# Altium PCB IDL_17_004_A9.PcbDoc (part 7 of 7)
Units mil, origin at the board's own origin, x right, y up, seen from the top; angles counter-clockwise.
Board outline 9493.25 x 7199.68 mil, 6 copper layers (Top Layer - SIG1, Layer 2 - GND1, Layer 3 - PWR1, Layer 4 - PWR2, Layer 5 - GND2, Bottom Layer - SIG2), stack 60.592 mil thick; 403 components, 274 nets, 1834 pads, 1849 vias.
Unrouted connection lines stored in the file: 1.
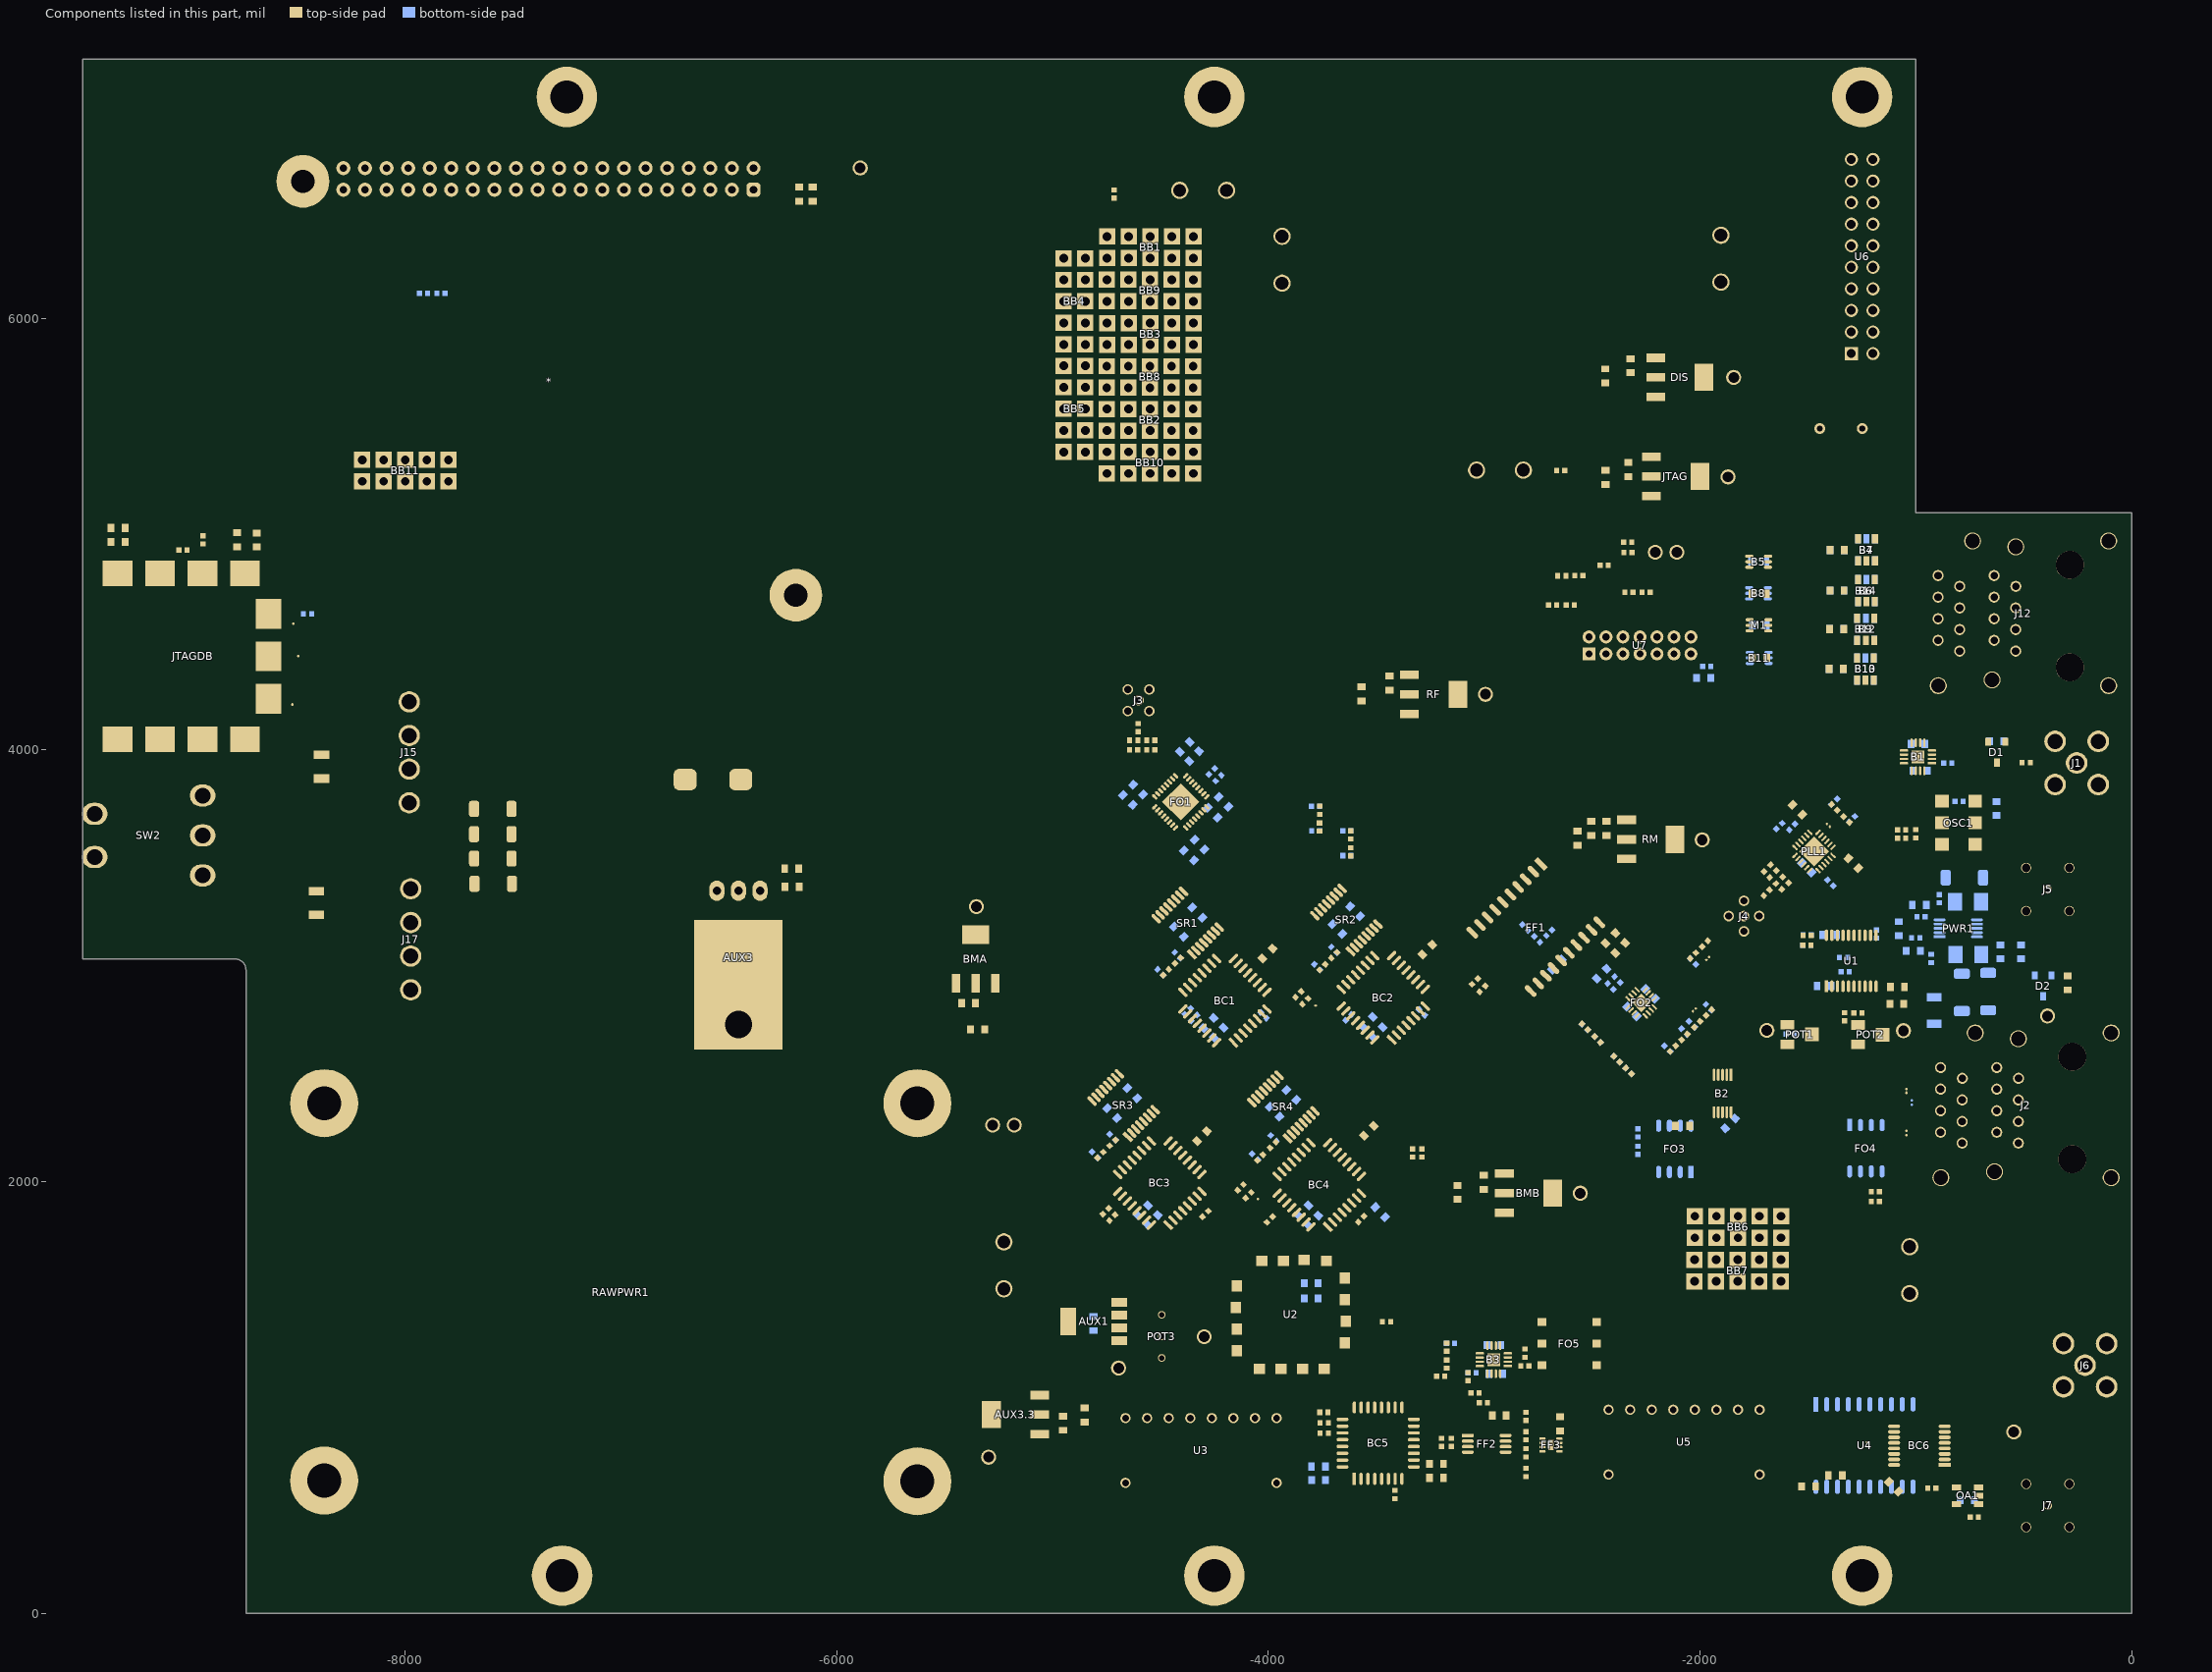
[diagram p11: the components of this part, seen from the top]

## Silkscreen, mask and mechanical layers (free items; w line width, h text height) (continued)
Drill Drawing:
  drawing of 873 lines, arcs and shapes, not listed
  text "Notes:" at -13256.02,10317 h130
  text "Table 1a: Layer Stack Details for IDL_15_039 Rev.A (Imperial Units)" at -2323.82,10266.73 h98.43
  text "11. PCB manufacturer may use tear drops to improve annular rings as long as DRC rules are followed" at -7919.02,10212 h100
  text "1. Board shall be fabricated - performace class II as per IPC-6011 and IPC6012" at -13256.02,10192 h100
  text "Layer" at -3102.3,10093.62 h60
  text "Name" at -2692.39,10093.62 h60
  text "Material" at -1462.74,10093.62 h60
  text "Thickness" at -602.97,10093.62 h60
  text "Constant" at 46.86,10093.62 h60
  text "Board Layer Stack" at 616.72,10093.62 h60
  text "Board Layer Stack" at 1736.41,10093.62 h60
  text "Symbol" at 3760.5,10092.37 h72
  text "Hit Count" at 4266.37,10092.37 h72
  text "Finished Hole Size" at 4964.18,10092.37 h72
  text "Plated" at 6309.79,10092.37 h72
  text "Hole Type" at 6815.66,10092.37 h72
  text "12. All via connections to power and ground planes are solid" at -7919.02,10072 h100
  text "2. PCB manufacturer logo, P/N, revision and/or date code of manufacturing" at -13256.02,10067 h100
  text "1" at -3102.3,9973.62 h60
  text "Top Overlay" at -2692.39,9973.62 h60
  text "shall be printed in top solder mask (not over pcb traces, allowed over copper plane)." at -13156.02,9967 h100
  text "1" at 4266.37,9942.37 h60
  text "125.98mil (3.200mm)" at 4964.18,9942.37 h60
  text "PTH" at 6309.79,9942.37 h60
  text "Round" at 6815.66,9942.37 h60
  text "13. All unconnected pads on inner signal layers are removed" at -7919.02,9932 h100
  text "I" at 3742.51,9932.38 h66.67
  text "The date code shall be in the format: \"WWYY\" where WW=week and YY= year, max height 0.15 inches" at -13156.02,9867 h100
  text "2" at -3102.3,9853.62 h60
  text "Top Solder" at -2692.39,9853.62 h60
  text "Solder Resist" at -1462.74,9853.62 h60
  text "0.40mil" at -602.97,9853.62 h60
  text "3.5" at 46.86,9853.62 h60
  text "14. All finished boards are to be 100% electrically tested" at -7919,9792 h100
  text "2" at 4266.37,9792.37 h60
  text "27.56mil (0.700mm)" at 4964.18,9792.37 h60
  text "PTH" at 6309.79,9792.37 h60
  text "Round" at 6815.66,9792.37 h60
  text "D" at 3731.41,9782.38 h66.67
  text "3. Silkscreen on both sides" at -13256.02,9742 h100
  text "3" at -3102.3,9733.62 h60
  text "Top Layer - SIG1" at -2692.39,9733.62 h60
  text "Copper" at -1462.74,9733.62 h60
  text "1.38mil" at -602.97,9733.62 h60
  text "15. Unless otherwise indicated, all linear toleracnes shall be XX.X +/-0.2mm and XX.XX +/- 0.1mm" at -7919.02,9652 h100
  text "2" at 4266.37,9642.37 h60
  text "28.00mil (0.711mm)" at 4964.18,9642.37 h60
  text "PTH" at 6309.79,9642.37 h60
  text "Round" at 6815.66,9642.37 h60
  text "E" at 3731.41,9632.38 h66.67
  text "4. Material: high temperature FR4 class epoxy glass rated UL94V-0. UL symbol and rating shall be marked farside" at -13256.02,9617 h100
  text "4" at -3102.3,9613.62 h60
  text "Dielectric 1" at -2692.39,9613.62 h60
  text "FR-4" at -1462.74,9613.62 h60
  text "9.00mil" at -602.97,9613.62 h60
  text "4.6" at 46.86,9613.62 h60
  text "35um copper for external layers and 18um for all internal layers" at -13156,9517 h100
  text "16. Gerber file GM1 shows board outline (milling line)" at -7919.02,9511.98 h100
  text "5" at -3102.3,9493.62 h60
  text "Layer 2 - GND1" at -2692.39,9493.62 h60
  text "Copper" at -1462.74,9493.62 h60
  text "0.71mil" at -602.97,9493.62 h60
  text "2" at 4266.37,9492.37 h60
  text "108.27mil (2.750mm)" at 4964.18,9492.37 h60
  text "PTH" at 6309.79,9492.37 h60
  text "Round" at 6815.66,9492.37 h60
  text "G" at 3731.41,9482.38 h66.67
  text "Must be RoHS compliant and survive a lead-free assembly max reflow of 260 deg C (5 passes)" at -13156.02,9417 h100
  text "6" at -3102.3,9373.62 h60
  text "Dielectric 2" at -2692.39,9373.62 h60
  text "FR-4" at -1462.74,9373.62 h60
  text "14.00mil" at -602.97,9373.62 h60
  text "4.6" at 46.86,9373.62 h60
  text "17. Table 1 shows Layer stack details" at -7919.03,9371.97 h100
  text "3" at 4266.37,9342.37 h60
  text "25.00mil (0.635mm)" at 4964.18,9342.37 h60
  text "PTH" at 6309.79,9342.37 h60
  text "Round" at 6815.66,9342.37 h60
  text "B" at 3731.41,9332.38 h66.67
  text "Td rating: >340 deg C" at -13106.02,9292 h100
  text "7" at -3102.3,9253.62 h60
  text "Layer 3 - PWR1" at -2692.39,9253.62 h60
  text "Copper" at -1462.74,9253.62 h60
  text "0.71mil" at -602.97,9253.62 h60
  text "4" at 4266.37,9192.37 h60
  text "130.00mil (3.302mm)" at 4964.18,9192.37 h60
  text "NPTH" at 6309.79,9192.37 h60
  text "Round" at 6815.66,9192.37 h60
  text "Tg = 150 deg C (min)" at -13101.98,9181.74 h100
  text "18. Layer 2, 3, 4, 5 are in negative image" at -8076.82,9154.94 h100
  text "8" at -3102.3,9133.62 h60
  text "Dielectric 3" at -2692.39,9133.62 h60
  text "FR-4" at -1462.74,9133.62 h60
  text "9.00mil" at -602.97,9133.62 h60
  text "4.2" at 46.86,9133.62 h60
  text "4" at 4266.37,9042.37 h60
  text "157.48mil (4.000mm)" at 4964.18,9042.37 h60
  text "PTH" at 6309.79,9042.37 h60
  text "Round" at 6815.66,9042.37 h60
  text "9" at -3102.3,9013.62 h60
  text "Layer 4 - PWR2" at -2692.39,9013.62 h60
  text "Copper" at -1462.74,9013.62 h60
  text "0.71mil" at -602.97,9013.62 h60
  text "Additional notes:" at -7910.38,8999.71 h130
  text "5. Solder mask: SMOBC per IPC-SM-840C, class T must be Rohs compliant, 0.001\" max measured over bare copper plating," at -13256.02,8942 h100
  text "10" at -3102.3,8893.62 h60
  text "Dielectric 4" at -2692.39,8893.62 h60
  text "FR-4" at -1462.74,8893.62 h60
  text "14.00mil" at -602.97,8893.62 h60
  text "4.6" at 46.86,8893.62 h60
  text "5" at 4266.37,8892.37 h60
  text "72.83mil (1.850mm)" at 4964.18,8892.37 h60
  text "PTH" at 6309.79,8892.37 h60
  text "Round" at 6815.66,8892.37 h60
  text "H" at 3731.41,8882.38 h66.67
  text "A1. Finished board thickness = 62mils +/- 10%; measured over top/bottom copper and solder mask" at -7910.36,8859.71 h100
  text "must clear all lands as indicated on gerber solder mask layers, color= GREEN" at -13156.02,8842 h100
  text "11" at -3102.3,8773.62 h60
  text "Layer 5 - GND2" at -2692.39,8773.62 h60
  text "Copper" at -1462.74,8773.62 h60
  text "0.71mil" at -602.97,8773.62 h60
  text "6" at 4266.37,8742.37 h60
  text "152.00mil (3.861mm)" at 4964.18,8742.37 h60
  text "PTH" at 6309.79,8742.37 h60
  text "Round" at 6815.66,8742.37 h60
  text "6. Finish: electro-less nickel immersion gold (ENIG), 0.05-0.125 mil Au over 3-6 mil Ni - over bare copper only" at -13256.23,8688.18 h100
  text "12" at -3102.3,8653.62 h60
  text "Dielectric 5" at -2692.39,8653.62 h60
  text "FR-4" at -1462.74,8653.62 h60
  text "9.00mil" at -602.97,8653.62 h60
  text "4.6" at 46.86,8653.62 h60
  text "8" at 4266.37,8592.37 h60
  text "70.87mil (1.800mm)" at 4964.18,8592.37 h60
  text "PTH" at 6309.79,8592.37 h60
  text "Round" at 6815.66,8592.37 h60
  text "7. Solderability test: Category 2 of J-STD-003" at -13256.02,8542 h100
  text "13" at -3102.3,8533.62 h60
  text "Bottom Layer - SIG2" at -2692.39,8533.62 h60
  text "Copper" at -1462.74,8533.62 h60
  text "1.38mil" at -602.97,8533.62 h60
  text "10" at 4266.37,8442.37 h60
  text "33.07mil (0.840mm)" at 4964.18,8442.37 h60
  text "PTH" at 6309.79,8442.37 h60
  text "Round" at 6815.66,8442.37 h60
  text "A" at 3731.41,8432.38 h66.67
  text "14" at -3102.3,8413.62 h60
  text "Bottom Solder" at -2692.39,8413.62 h60
  text "Solder Resist" at -1462.74,8413.62 h60
  text "0.40mil" at -602.97,8413.62 h60
  text "3.5" at 46.86,8413.62 h60
  text "8. Finished boards shall not have nicks, scratches, voids, exposed copper, poor plating or misdrilled holes" at -13256.02,8392 h100
  text "15" at -3102.3,8293.62 h60
  text "Bottom Overlay" at -2692.39,8293.62 h60
  text "10" at 4266.37,8292.37 h60
  text "70.00mil (1.778mm)" at 4964.18,8292.37 h60
  text "PTH" at 6309.79,8292.37 h60
  text "Round" at 6815.66,8292.37 h60
  text "9. All holes sizes are after plating" at -13256.02,8242 h100
  text "11" at 4266.37,8142.37 h60
  text "39.37mil (1.000mm)" at 4964.18,8142.37 h60
  text "PTH" at 6309.79,8142.37 h60
  text "Round" at 6815.66,8142.37 h60
  text "10. PCB manufacturer may add copper thieving as needed to improve manufacturability," at -13306.02,8092 h100
  text "Table 2: NC Drill Details for IDL_15_039 Rev.A" at -1161.27,8006.12 h98.43
  text "thieving to be 0.030\" round pads at 0.050\" spacing." at -13156.02,7992 h100
  text "12" at 4266.37,7992.37 h60
  text "60.00mil (1.524mm)" at 4964.18,7992.37 h60
  text "PTH" at 6309.79,7992.37 h60
  text "Round" at 6815.66,7992.37 h60
  text "Thieving will have a minimum of 0.100\" clearance from existing copper and should not be placed under surface mounted devices" at -13156.02,7892 h100
  text "12" at 4266.37,7842.37 h60
  text "66.93mil (1.700mm)" at 4964.18,7842.37 h60
  text "PTH" at 6309.79,7842.37 h60
  text "Round" at 6815.66,7842.37 h60
  text "14" at 4266.37,7692.37 h60
  text "33.00mil (0.838mm)" at 4964.18,7692.37 h60
  text "PTH" at 6309.79,7692.37 h60
  text "Round" at 6815.66,7692.37 h60
  text "18" at 4266.37,7542.37 h60
  text "50.00mil (1.270mm)" at 4964.18,7542.37 h60
  text "PTH" at 6309.79,7542.37 h60
  text "Round" at 6815.66,7542.37 h60
  text "20" at 4266.37,7392.37 h60
  text "31.50mil (0.800mm)" at 4964.18,7392.37 h60
  text "PTH" at 6309.79,7392.37 h60
  text "Round" at 6815.66,7392.37 h60
  text "20" at 4266.37,7242.37 h60
  text "41.00mil (1.041mm)" at 4964.18,7242.37 h60
  text "PTH" at 6309.79,7242.37 h60
  text "Round" at 6815.66,7242.37 h60
  text "72" at 4266.37,7092.37 h60
  text "35.43mil (0.900mm)" at 4964.18,7092.37 h60
  text "PTH" at 6309.79,7092.37 h60
  text "Round" at 6815.66,7092.37 h60
  text "C" at 3731.41,7082.38 h66.67
  text "110" at 4266.37,6942.37 h60
  text "40.00mil (1.016mm)" at 4964.18,6942.37 h60
  text "PTH" at 6309.79,6942.37 h60
  text "Round" at 6815.66,6942.37 h60
  text "163" at 4266.37,6792.37 h60
  text "11.81mil (0.300mm)" at 4964.18,6792.37 h60
  text "PTH" at 6309.79,6792.37 h60
  text "Round" at 6815.66,6792.37 h60
  text "F" at 3731.41,6782.38 h66.67
  text "1686" at 4266.37,6642.37 h60
  text "12.00mil (0.305mm)" at 4964.18,6642.37 h60
  text "PTH" at 6309.79,6642.37 h60
  text "Round" at 6815.66,6642.37 h60
  text "2195 Total" at 4266.37,6492.37 h60

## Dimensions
-9036.8,4436 to -10463,0 on Dimensions
-8742.67,-0.11 to -9976.37,3601.18 on Dimensions
-9491.14,7199.89 to -8735.4,0 on Dimensions
-8735.4,0 to -9496.02,3031.5 on Dimensions
-8735.4,0 to -9499,50 on Dimensions
63,-739 to 172.65,1153.15 on Mech 11
63,-739 to 126,500 on Mech 11
63,-739 to 126,2100 on Mech 11
63,-739 to 126,3301 on Mech 11
63,-739 to 144,6300 on Mech 11
63,-739 to 126,4300 on Mech 11
63,-739 to 0.5,-739 on Mech 11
